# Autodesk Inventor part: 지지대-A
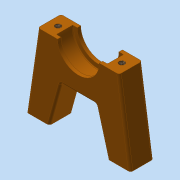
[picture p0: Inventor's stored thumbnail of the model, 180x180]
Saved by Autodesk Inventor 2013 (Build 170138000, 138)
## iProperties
Created: 2018-01
Part Number: 지지대-A
Material: 알루미늄 6061
Document SubType Name: Modeling
Designer: mduedu
Density: 2.71 g/cm^3
Mass: 21.9456 g
Surface Area: 38.5771 cm^2
Volume: 8.09801 cm^3
Author: mduedu
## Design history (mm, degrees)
sketch "스케치1"
  geometry: L1 (-22.5, 0)-(22.5, 0); L2 (22.5, 0)-(17.5, 34); L3 (17.5, 34)-(-17.5, 34); L4 (-17.5, 34)-(-22.5, 0); 3 further points
  constraints: 8 end point, 2 midpoint, 1 coincident, 1 horizontal, 1 parallel, 1 vertical alignment
  dimensions: "d0" = 45 distance of L1.start L1.end; "d3" = 35 distance of L2.end L3.end; "d4" = 34 vertical distance of L1.end L2.end
extrude "돌출1" new body sketch "스케치1" stored distance "d5" = 10; taper "d6" = 0 deg
sketch "스케치2"
  geometry: L1 (-12.5, 0)-(12.5, 0); L2 (12.5, 0)-(7.5, 18); L3 (7.5, 18)-(-7.5, 18); L4 (-7.5, 18)-(-12.5, 0); L5 (-22.5, 0)-(22.5, 0) reference; 4 further points
  constraints: 8 end point, 4 midpoint, 1 horizontal, 1 parallel, 1 vertical alignment
  dimensions: "d7" = 10 distance of L1.start L5.start; "d8" = 10 distance of L1.end L5.end (derived); "d9" = 15 distance of L2.end L3.end; "d10" = 18 distance between parallel lines of L1 L3
extrude "돌출2" cut sketch "스케치2" stored distance "d11" = 10; taper "d12" = 0 deg
sketch "스케치3"
  geometry: L1 (-17.5, 34)-(17.5, 34) reference; C1 r 11 at (0, 34); C2 r 9 at (0, 34); 1 further point
  constraints: 2 centre point, 1 coincident, 1 midpoint
  dimensions: "d13" = 22 diameter of C1; "d16" = 18 diameter of C2
extrude "돌출3" cut sketch "스케치3" stored distance "d14" = 7; taper "d15" = 0 deg
extrude "돌출4" cut sketch "스케치3" stored distance "d17" = 7; taper "d18" = 0 deg
fillet "모깎기1" dims "d19" = 0.3
fillet "모깎기2" dims "d20" = 1
fillet "모깎기3" dims "d21" = 1
fillet "모깎기4" dims "d22" = 1
sketch "스케치4"
  geometry: 2 further points
  constraints: 2 other
hole "구멍1" sketch "스케치4" at (-22.771, -3.5), (4.771, -3.5) diameter "d23" = 2.459; stored, may be unused: countersink angle "d27" = 90 deg, drill point angle "d29" = 120 deg; dims "d24" = 4.5, "d25" = 4, "d26" = 2, "d28" = 6
sketch "스케치5"
  geometry: 4 further points
  constraints: 4 other
hole "구멍2" sketch "스케치5" at (40, 4), (5, -27), (40, -27), (5, 4) diameter "d30" = 2.459; stored, may be unused: countersink angle "d34" = 90 deg, drill point angle "d36" = 120 deg; dims "d31" = 6.9, "d32" = 4, "d33" = 2, "d35" = 8.4
node "솔리드1"
